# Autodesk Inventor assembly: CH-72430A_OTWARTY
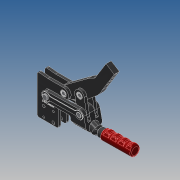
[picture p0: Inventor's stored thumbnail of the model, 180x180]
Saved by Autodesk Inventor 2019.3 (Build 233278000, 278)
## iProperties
Company: Î¢ÈíÖÐ¹ú
Created: 2012-10
Part Number: CH-72430A_OTWARTY
Material: Ogólny
Description: STEP AP203
Document SubType Name: Assembly
Designer: CADENGINEERING4
Sending System: SolidWorks 2010
Preprocessor: SwSTEP 2.0
Title: CH-72430A.STEP
Author: Î¢ÈíÓÃ»§
Revision Number: ÈÎºÎ
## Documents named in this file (12)
- E:\CAD_CLAMPS\Heavy duty weldables\CH-72430A_DODAC\CH-72430A_OTWARTY.iam
- E:\CAD_CLAMPS\Heavy duty weldables\CH-72430A_DODAC\72425-11.ipt
- E:\CAD_CLAMPS\Heavy duty weldables\CH-72430A_DODAC\72425-06.ipt
- E:\CAD_CLAMPS\Heavy duty weldables\CH-72430A_DODAC\72425-03.ipt
- E:\CAD_CLAMPS\Heavy duty weldables\CH-72430A_DODAC\72425-09.ipt
- E:\CAD_CLAMPS\Heavy duty weldables\CH-72430A_DODAC\M12.ipt
- E:\CAD_CLAMPS\Heavy duty weldables\CH-72430A_DODAC\72425-10.ipt
- E:\CAD_CLAMPS\Heavy duty weldables\CH-72430A_DODAC\72425-08.ipt
- E:\CAD_CLAMPS\Heavy duty weldables\CH-72430A_DODAC\72425-04.ipt
- E:\CAD_CLAMPS\Heavy duty weldables\CH-72430A_DODAC\CH-72430A-02.ipt
- E:\CAD_CLAMPS\Heavy duty weldables\CH-72430A_DODAC\CH-72430A-01.ipt
- E:\CAD_CLAMPS\Heavy duty weldables\CH-72430A_DODAC\72425-07.ipt
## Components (20 placed, 20 different names)
1. 72425-11_1 — Zestawiające:1, Zestawiające:2, Kątowe:1
2. 72425-06_2 — Zestawiające:16, Równoległe:5
3. 72425-03_3 — Zestawiające:3, Zestawiające:5, Zestawiające:19, Zestawiające:20, Zestawiające:22, Równoległe:8
4. 72425-09_4
5. 72425-06_5 — Zestawiające:10, Zestawiające:13, Zestawiające:18, Równoległe:7
6. M12_6
7. 72425-06_7 — Zestawiające:3, Zestawiające:6, Zestawiające:7, Równoległe:8
8. 72425-10_8 — Zestawiające:25
9. 72425-06_9 — Zestawiające:11, Zestawiające:12
10. 72425-06_10 — Zestawiające:15, Równoległe:4, Zestawiające:17, Równoległe:6
11. 72425-06_11
12. 72425-06_12
13. 72425-08_13 — Zestawiające:18, Równoległe:7, Zestawiające:19
14. 72425-08_14 — Zestawiające:17, Równoległe:6, Zestawiające:24
15. 72425-03_15 — Zestawiające:4, Równoległe:2, Zestawiające:5, Zestawiające:21
16. 72425-04_16 — Zestawiające:1, Zestawiające:2, Kątowe:1, Zestawiające:7, Zestawiające:14, Równoległe:3, Zestawiające:20, Zestawiające:21, Zestawiające:25, Kątowe:2
17. 72425-06_17 — Zestawiające:4, Równoległe:2, Zestawiające:6
18. CH-72430A-02_18 — Zestawiające:10, Zestawiające:11, Zestawiające:12, Zestawiające:13, Zestawiające:22, Zestawiające:23, Zestawiające:24
19. CH-72430A-01_19 — Zestawiające:15, Zestawiające:16, Równoległe:4, Równoległe:5, Zestawiające:23, Kątowe:2
20. 72425-07_20 — Zestawiające:14, Równoległe:3
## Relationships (32: Mate 23, Flush 7, Angle 2)
- Zestawiające:1 [Mate]: 72425-11_1 ↔ 72425-04_16
- Zestawiające:2 [Mate]: 72425-11_1 ↔ 72425-04_16
- Kątowe:1 [Angle]: 72425-11_1 ↔ 72425-04_16
- Zestawiające:3 [Mate]: 72425-03_3 ↔ 72425-06_7
- Zestawiające:4 [Mate]: 72425-03_15 ↔ 72425-06_17
- Równoległe:2 [Flush]: 72425-03_15 ↔ 72425-06_17
- Zestawiające:5 [Mate]: 72425-03_3 ↔ 72425-03_15
- Zestawiające:6 [Mate]: 72425-06_7 ↔ 72425-06_17
- Zestawiające:7 [Mate]: 72425-06_7 ↔ 72425-04_16
- Zestawiające:10 [Mate]: 72425-06_5 ↔ CH-72430A-02_18
- Zestawiające:11 [Mate]: 72425-06_9 ↔ CH-72430A-02_18
- Zestawiające:12 [Mate]: 72425-06_9 ↔ CH-72430A-02_18
- Zestawiające:13 [Mate]: 72425-06_5 ↔ CH-72430A-02_18
- Zestawiające:14 [Mate]: 72425-04_16 ↔ 72425-07_20
- Równoległe:3 [Flush]: 72425-04_16 ↔ 72425-07_20
- Zestawiające:15 [Mate]: 72425-06_10 ↔ CH-72430A-01_19
- Zestawiające:16 [Mate]: 72425-06_2 ↔ CH-72430A-01_19
- Równoległe:4 [Flush]: 72425-06_10 ↔ CH-72430A-01_19
- Równoległe:5 [Flush]: 72425-06_2 ↔ CH-72430A-01_19
- Zestawiające:17 [Mate]: 72425-06_10 ↔ 72425-08_14
- Równoległe:6 [Flush]: 72425-06_10 ↔ 72425-08_14
- Zestawiające:18 [Mate]: 72425-06_5 ↔ 72425-08_13
- Równoległe:7 [Flush]: 72425-06_5 ↔ 72425-08_13
- Zestawiające:19 [Mate]: 72425-03_3 ↔ 72425-08_13
- Zestawiające:20 [Mate]: 72425-03_3 ↔ 72425-04_16
- Zestawiające:21 [Mate]: 72425-03_15 ↔ 72425-04_16
- Zestawiające:22 [Mate]: 72425-03_3 ↔ CH-72430A-02_18
- Równoległe:8 [Flush]: 72425-03_3 ↔ 72425-06_7
- Zestawiające:23 [Mate]: CH-72430A-02_18 ↔ CH-72430A-01_19
- Zestawiające:24 [Mate]: 72425-08_14 ↔ CH-72430A-02_18
- Zestawiające:25 [Mate]: 72425-10_8 ↔ 72425-04_16
- Kątowe:2 [Angle]: 72425-04_16 ↔ CH-72430A-01_19
